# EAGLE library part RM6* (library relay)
Power Relay SCHRACK 3 pole 10 A, DC- or AC-coil Source: http://www.schrack.com/.. 5832.pdf
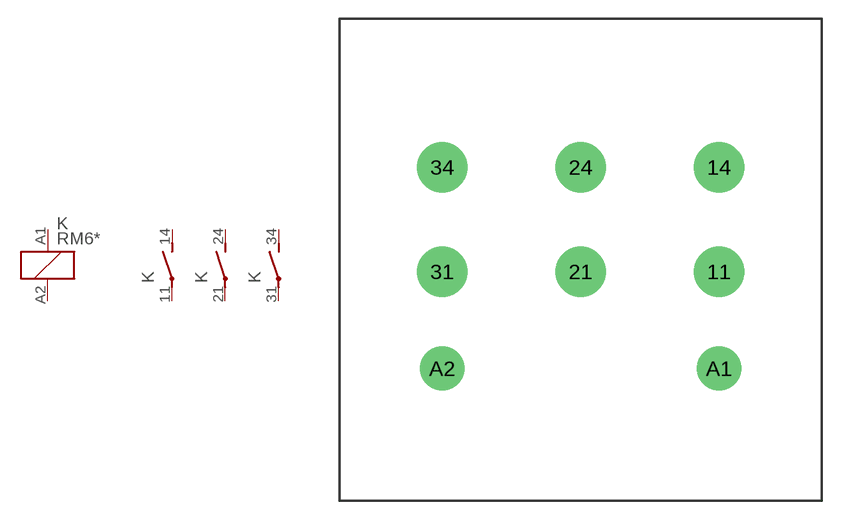
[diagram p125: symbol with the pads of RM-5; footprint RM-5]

Designator prefix K; gates 1=K 2=S 3=S 4=S

## RM607R06 (OC_FARNELL: unknown; OC_NEWARK: unknown), RM607R12 (OC_FARNELL: unknown; OC_NEWARK: unknown), RM607R24 (OC_FARNELL: unknown; OC_NEWARK: unknown), RM607R48 (OC_FARNELL: unknown; OC_NEWARK: unknown), RM607R60 (OC_FARNELL: unknown; OC_NEWARK: unknown), RM607S15 (OC_FARNELL: unknown; OC_NEWARK: unknown), RM607T30 (OC_FARNELL: unknown; OC_NEWARK: unknown), RM607V00 (OC_FARNELL: unknown; OC_NEWARK: unknown), RM607506 (OC_FARNELL: unknown; OC_NEWARK: unknown), RM607512 (OC_FARNELL: unknown; OC_NEWARK: unknown), RM607524 (MPN: RM607524; OC_FARNELL: unknown; OC_NEWARK: 48M7685), RM607548 (OC_FARNELL: unknown; OC_NEWARK: unknown), RM607560 (OC_FARNELL: unknown; OC_NEWARK: unknown), RM607615 (OC_FARNELL: unknown; OC_NEWARK: unknown), RM607730 (MPN: RM607730; OC_FARNELL: unknown; OC_NEWARK: 03M2867), RM607900 (OC_FARNELL: unknown; OC_NEWARK: unknown)  [RM-5]
11  2:P  pas
14  2:S  pas
21  3:P  pas
24  3:S  pas
31  4:P  pas
34  4:S  pas
A1  1:1  pas
A2  1:2  pas

## Footprint RM-5 (pad centres in mm)
Power Relay SCHRACK 3 pole 10 A, DC- or AC-coil Source: http://www.schrack.com/.. 5832.pdf
drill 2 pad 4 round: 11 11,-0.95; 14 11,7.35; 21 0,-0.95; 24 0,7.35; 31 -11,-0.95; 34 -11,7.35
drill 2 pad 3.5 round: A1 11,-8.65; A2 -11,-8.65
